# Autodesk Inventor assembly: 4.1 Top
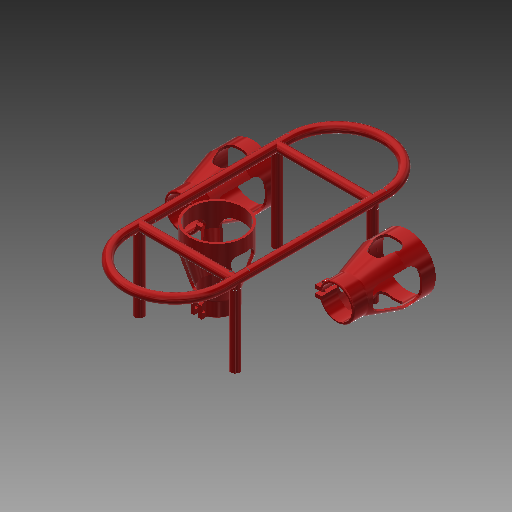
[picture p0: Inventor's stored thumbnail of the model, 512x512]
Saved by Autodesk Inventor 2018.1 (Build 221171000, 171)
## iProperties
Created: 2018-06
Part Number: 4.1 Top
Document SubType Name: Assembly
Designer: Ryan
Author: Ryan
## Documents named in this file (10)
- C:\Users\Ryan\Desktop\Seaperch 2018\ROV V4.2\4.1\4.1 Top.iam
- C:\Users\Ryan\Desktop\Seaperch 2018\ROV V4.2\4.1\Bumpers.ipt
- C:\Users\Ryan\Desktop\Seaperch 2018\ROV V4.2\4.1\Top 90 90 T Left.ipt
- C:\Users\Ryan\Desktop\Seaperch 2018\ROV V4.2\4.1\Top 90 90 T Right.ipt
- C:\Users\Ryan\Desktop\Seaperch 2018\ROV V4.2\4.1\Top Back Motor YD Rod Left.ipt
- C:\Users\Ryan\Desktop\Seaperch 2018\ROV V4.2\4.1\Top Back Motor YD Rod Right.ipt
- C:\Users\Ryan\Desktop\Seaperch 2018\ROV V4.2\4.1\Top Back XD Rod.ipt
- C:\Users\Ryan\Desktop\Seaperch 2018\ROV V4.2\4.1\Top Front Motor XD Rod.ipt
- C:\Users\Ryan\Desktop\Seaperch 2018\ROV V4.2\4.1\Top Front YD Rod.ipt
- C:\Users\Ryan\Desktop\Seaperch 2018\ROV V4.2\4.1\Top ZD Rod.ipt
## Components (14 placed, 9 different names)
1. Bumpers:1 — Mate:1, Mate:2, Mate:3, Mate:4, Mate:7, Angle:1, Angle:4, Mate:24
2. Bumpers:2 — Mate:1, Mate:2, Mate:5, Mate:6, Mate:9, Angle:2, Mate:25
3. Top 90 90 T Left:1 — Mate:3, Mate:4, Mate:8, Mate:17, Mate:20, Mate:21, Mate:26, Mate:31
4. Top 90 90 T Left:2 — Mate:5, Mate:6, Mate:10, Mate:11, Mate:12, Mate:15, Mate:30
5. Top 90 90 T Right:1 — Mate:9, Mate:10, Mate:13, Mate:14, Mate:16, Mate:28
6. Top 90 90 T Right:2 — Mate:7, Mate:8, Mate:18, Angle:3, Angle:4, Mate:19, Mate:22, Mate:23, Mate:27, Mate:29
7. Top Back Motor YD Rod Left:1 — Mate:11, Mate:12, Angle:1
8. Top Back Motor YD Rod Right:1 — Mate:13, Mate:14, Angle:2
9. Top Back XD Rod:1 — Mate:15, Mate:16
10. Top Front Motor XD Rod:1 — Mate:17, Mate:18, Angle:3
11. Top Front YD Rod:1 — Mate:19, Mate:22, Mate:23
12. Top Front YD Rod:2 — Mate:20, Mate:21
13. Top ZD Rod:1 — Mate:24, Mate:25, Mate:26, Mate:30, Mate:31
14. Top ZD Rod:2 — Mate:27, Mate:28, Mate:29
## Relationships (35: Mate 31, Angle 4)
- Mate:1: Bumpers:1 ↔ Bumpers:2
- Mate:2: Bumpers:1 ↔ Bumpers:2
- Mate:3: Bumpers:1 ↔ Top 90 90 T Left:1
- Mate:4: Bumpers:1 ↔ Top 90 90 T Left:1
- Mate:5: Bumpers:2 ↔ Top 90 90 T Left:2
- Mate:6: Bumpers:2 ↔ Top 90 90 T Left:2
- Mate:7: Bumpers:1 ↔ Top 90 90 T Right:2
- Mate:8: Top 90 90 T Left:1 ↔ Top 90 90 T Right:2
- Mate:9: Bumpers:2 ↔ Top 90 90 T Right:1
- Mate:10: Top 90 90 T Left:2 ↔ Top 90 90 T Right:1
- Mate:11: Top 90 90 T Left:2 ↔ Top Back Motor YD Rod Left:1
- Mate:12: Top 90 90 T Left:2 ↔ Top Back Motor YD Rod Left:1
- Mate:13: Top 90 90 T Right:1 ↔ Top Back Motor YD Rod Right:1
- Mate:14: Top 90 90 T Right:1 ↔ Top Back Motor YD Rod Right:1
- Angle:1: Bumpers:1 ↔ Top Back Motor YD Rod Left:1
- Angle:2: Bumpers:2 ↔ Top Back Motor YD Rod Right:1
- Mate:15: Top 90 90 T Left:2 ↔ Top Back XD Rod:1
- Mate:16: Top 90 90 T Right:1 ↔ Top Back XD Rod:1
- Mate:17: Top 90 90 T Left:1 ↔ Top Front Motor XD Rod:1
- Mate:18: Top 90 90 T Right:2 ↔ Top Front Motor XD Rod:1
- Angle:3: Top 90 90 T Right:2 ↔ Top Front Motor XD Rod:1
- Angle:4: Bumpers:1 ↔ Top 90 90 T Right:2
- Mate:19: Top 90 90 T Right:2 ↔ Top Front YD Rod:1
- Mate:20: Top 90 90 T Left:1 ↔ Top Front YD Rod:2
- Mate:21: Top 90 90 T Left:1 ↔ Top Front YD Rod:2
- Mate:22: Top 90 90 T Right:2 ↔ Top Front YD Rod:1
- Mate:23: Top 90 90 T Right:2 ↔ Top Front YD Rod:1
- Mate:24: Bumpers:1 ↔ Top ZD Rod:1
- Mate:25: Bumpers:2 ↔ Top ZD Rod:1
- Mate:26: Top 90 90 T Left:1 ↔ Top ZD Rod:1
- Mate:27: Top 90 90 T Right:2 ↔ Top ZD Rod:2
- Mate:28: Top 90 90 T Right:1 ↔ Top ZD Rod:2
- Mate:29: Top 90 90 T Right:2 ↔ Top ZD Rod:2
- Mate:30: Top 90 90 T Left:2 ↔ Top ZD Rod:1
- Mate:31: Top 90 90 T Left:1 ↔ Top ZD Rod:1
